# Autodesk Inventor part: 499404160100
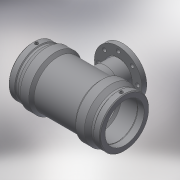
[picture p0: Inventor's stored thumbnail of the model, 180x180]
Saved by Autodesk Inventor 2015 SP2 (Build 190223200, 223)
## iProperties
Created: 2017-06
Part Number: 499404160100
Material: Generic
Description: PLASSON FLANGED TEE 160x100x160
Document SubType Name: Modeling
Designer: KIM
Mass: 57.3761 g
Surface Area: 241.06 cm^2
Volume: 57.3761 cm^3
Density: 1 g/cm^3
Appearance: Default
Author: KIM
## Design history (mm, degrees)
derived "499404.ipt"
feature "Solid1::499404.ipt"
tag "TaggingFeature1"
body "Solid1"
other parameters: "d14" = 17.6296, "d17" = 144, "d19" = 3.52592, "d20" = 168 deg, "d22" = 193.44, "d23" = 208, "d24" = 187.6368, "d25" = 135 deg, "d26" = 308, "d27" = 135 deg, "d29" = 106, "d35" = 15, "d39" = 5 deg, "d45" = 4, "d46" = 14, "d47" = 0, "d55" = 187.2, "d56" = 208, "d57" = 154, "d58" = 135 deg, "d59" = 86, "d60" = 86, "d61" = 135 deg, "d72" = 200.2, "d73" = 100.1, "d87" = 158, "d90" = 125, "d91" = 15 deg, "d93" = 22, "d95" = 4.74, "d97" = 18, "d100" = 0, "d102" = 360 deg, "d105" = 0, "d107" = 0, "d108" = 3, "d109" = 0, "d110" = 25.8, "d111" = 8.6, "L_1" = 86, "D_" = 208, "A_" = 106, "d_2" = 12, "t_" = 22, "d_1" = 158, "s_" = 18
